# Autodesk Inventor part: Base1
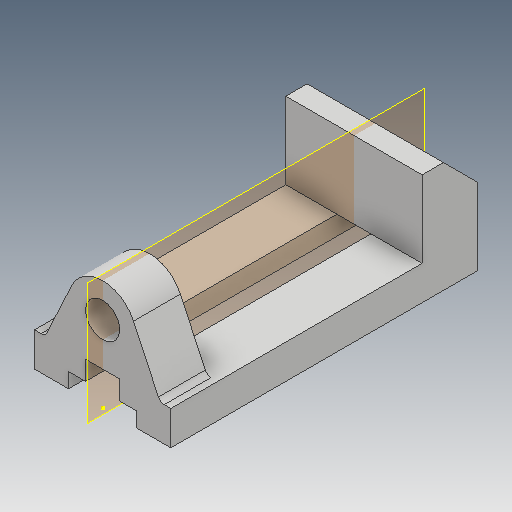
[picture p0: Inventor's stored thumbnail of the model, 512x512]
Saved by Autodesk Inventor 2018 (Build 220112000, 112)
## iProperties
Created: 2016-03
Part Number: Base1
Material: Generic
Document SubType Name: Modeling
Designer: Sandeep
Density: 1 g/cm^3
Appearance: Default
Author: Sandeep
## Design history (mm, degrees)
sketch "Sketch1"
  geometry: L1 (0, 0)-(0, 16); L2 (0, 16)-(118, 16); L3 (118, 16)-(118, 52); L4 (118, 52)-(144, 52); L5 (144, 52)-(144, 0); L6 (144, 0)-(0, 0)
  constraints: 12 end point, 3 perpendicular, 1 vertical
  dimensions: "d1" = 144 distance of L5.end L1.start; "d2" = 26 distance of L3.end L4.end; "d3" = 16 distance between parallel lines of L6 L2; "d4" = 36 distance between parallel lines of L2 L4
extrude "Extrusion1" new body sketch "Sketch1" stored distance "d5" = 64; taper "d6" = 0 deg
chamfer "Chamfer1" distance "d7" = 16; stored, may be unused: second distance "d8" = 16, angle "d9" = 45 deg
sketch "Sketch4"
  geometry: 1 further point
sketch "Sketch5"
  geometry: L1 (-16, 5.02)-(-42.762, 17.499); L2 (-42.762, 46.501)-(-16, 58.98); L3 (-52, 64)-(-52, 0) reference; L4 (-16, 32)-(-54.774, 32); L5 (-52, 64)-(-16, 64) reference; L6 (-16, 64)-(-16, 0) reference; L7 (-16, 5.02)-(-16, 58.98); L8 (0, 64)-(0, 0) reference; A1 r 16 centre (-36, 32) between (-42.762, 46.501) and (-42.762, 17.499); 1 further point
  constraints: 8 end point, 3 point on line, 3 tangent, 2 point on circle, 1 centre point, 1 collinear, 1 horizontal, 1 other
  dimensions: "d21" = 50 deg angle of L2 L1; "d22" = 36 distance from line of L8 A1.centre
extrude "Extrusion2" join sketch "Sketch5" distance "d23" = 22; taper "d24" = 0 deg
fillet "Fillet1" dims "d25" = 3
sketch "Sketch6"
  geometry: L1 (-36, 64)-(-36, 0) reference; C1 r 8 at (-36, 32); A1 r 16 centre (-36, 32) between (-42.762, 46.501) and (-42.762, 17.499) reference; 1 further point
  constraints: 1 centre point, 1 concentric, 1 midpoint
  dimensions: "d26" = 16 diameter of C1
extrude "Extrusion3" cut sketch "Sketch6" distance "d27" = 22; taper "d28" = 0 deg
sketch "Sketch7"
  geometry: L1 (0, 0)-(0, 64) reference; L2 (0, 16)-(-7, 16); L3 (-7, 16)-(-7, 24); L4 (-7, 24)-(-16, 24); L5 (-16, 3.109)-(-16, 60.891) reference; L6 (-16, 24)-(-16, 40); L7 (-7, 40)-(-7, 48); L8 (-7, 48)-(0, 48); L9 (0, 48)-(0, 16); L10 (-7, 40)-(-16, 40); L11 (-44, 32)-(-36, 32); 1 further point
  constraints: 18 end point, 6 point on line, 4 perpendicular, 2 horizontal, 1 collinear, 1 horizontal alignment, 4 other
  dimensions: "d29" = 32 distance between parallel lines of L2 L8; "d30" = 7 distance of L7.end L8.end; "d45" = 16 distance between parallel lines of L10 L4
extrude "Extrusion4" cut sketch "Sketch7" distance "d31" = 167.75; taper "d32" = 0 deg
sketch "Sketch8"
  geometry: L1 (144, 0)-(144, -16) reference; L2 (0, 0)-(144, 0) reference; L3 (0, -16)-(0, 0) reference; 3 further points
  dimensions: "d33" = 70 distance of point (108, -10) point (38, -10); "d35" = 10 distance from line of L2 point (108, -10); "d36" = 10 distance from line of L2 point (38, -10); "d46" = 38 distance from line of L3 point (38, -10)
hole "Hole1" sketch "Sketch8" at (38, -10), (108, -10) diameter "d37" = 4.917; stored, may be unused: countersink angle "d41" = 90 deg, drill point angle "d43" = 118 deg; dims "d38" = 12, "d39" = 4, "d40" = 2, "d42" = 10
workplane "Work Plane1"
mirror "Mirror1"
body "Solid1"
other parameters: "d10" = 16, "d13" = 7, "d14" = 16, "d44" = -32
